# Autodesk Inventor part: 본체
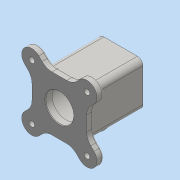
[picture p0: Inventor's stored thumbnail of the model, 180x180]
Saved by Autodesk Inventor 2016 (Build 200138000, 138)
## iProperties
Created: 2019-11
Part Number: 본체
Material: 일반
Document SubType Name: Modeling
Designer: user
Density: 1 g/cm^3
Appearance: 기본값
Author: user
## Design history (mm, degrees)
sketch "스케치1"
  geometry: L1 (49.497, 49.497)-(-49.497, -49.497); L2 (36.77, 62.225)-(-62.225, -36.77); L3 (-36.77, -62.225)-(62.225, 36.77); L4 (-49.497, 49.497)-(49.497, -49.497); L5 (-62.225, 36.77)-(36.77, -62.225); L6 (62.225, -36.77)-(-36.77, 62.225); L7 (0, 0)-(0, -25.456); L8 (49, 49)-(-49, 49); L9 (-49, 49)-(-49, -49); L10 (-49, -49)-(49, -49); L11 (49, -49)-(49, 49); L12 (49, 49)-(-49, -49); L13 (-49, 49)-(49, -49); A1 r 18 centre (49.497, 49.497) between (62.225, 36.77) and (36.77, 62.225); A2 r 18 centre (-49.497, -49.497) between (-62.225, -36.77) and (-36.77, -62.225); A3 r 18 centre (-49.497, 49.497) between (-36.77, 62.225) and (-62.225, 36.77); A4 r 18 centre (49.497, -49.497) between (36.77, -62.225) and (62.225, -36.77)
  constraints: 30 end point, 8 point on circle, 8 tangent, 4 centre point, 4 midpoint, 4 parallel, 1 horizontal, 1 perpendicular, 1 point on line, 1 vertical
  dimensions: "d0" = 70 distance of L7.start L1.end; "d1" = 36 diameter of A2; "d2" = 70 distance of L7.start L4.end; "d3" = 36 diameter of A4; "d4" = 90 deg angle of L4 L1; "d5" = 45 deg angle of L7 L1; "d6" = 98 distance of L9.end L10.end; "d7" = 98 distance of L8.end L9.end
extrude "돌출1" new body sketch "스케치1" distance "d8" = 12; taper "d9" = 0 deg
sketch "스케치2"
  geometry: L1 (-30, -40)-(30, -40); L2 (40, -30)-(40, 30); L3 (30, 40)-(-30, 40); L4 (-40, 30)-(-40, -30); L5 (-40, -40)-(40, 40); L6 (40, -40)-(-40, 40); A1 r 10 centre (-30, 30) between (-30, 40) and (-40, 30); A2 r 10 centre (-30, -30) between (-40, -30) and (-30, -40); A3 r 10 centre (30, -30) between (30, -40) and (40, -30); A4 r 10 centre (30, 30) between (40, 30) and (30, 40); 1 further point
  constraints: 12 end point, 8 point on circle, 8 point on line, 8 tangent, 4 centre point, 3 equal radius, 2 midpoint, 2 parallel, 1 horizontal, 1 perpendicular
  dimensions: "d10" = 80 distance of L6.end L5.end; "d11" = 80 distance of L6.start L5.end; "d56" = 10 radius of A1
extrude "돌출2" join sketch "스케치2" distance "d12" = 98; taper "d13" = 0 deg
sketch "스케치3"
  geometry: 2 further points
  constraints: 1 coincident
hole "구멍1" sketch "스케치3" at (0, 0) diameter "d14" = 50; stored, may be unused: countersink angle "d18" = 90 deg, drill point angle "d20" = 0 deg; dims "d15" = 6, "d16" = 4, "d17" = 2, "d19" = 12
sketch "스케치4"
  geometry: 2 further points
  constraints: 1 coincident
hole "구멍2" sketch "스케치4" at (0, 0) diameter "d21" = 50; stored, may be unused: countersink angle "d25" = 90 deg, drill point angle "d27" = 0 deg; dims "d22" = 6, "d23" = 70, "d24" = 86, "d26" = 12
node "작업 평면1"
sketch "스케치6"
  geometry: L1 (-23.544, 0)-(23.544, 0) reference; C1 r 20 at (0, 61); 1 further point
  constraints: 1 centre point, 1 vertical alignment
  dimensions: "d33" = 40 diameter of C1; "d34" = 61 distance from line of L1 C1.centre
extrude "돌출4" join sketch "스케치6" stored distance "d35" = 30; taper "d36" = 0 deg
sketch "스케치7"
  geometry: C1 r 20 at (0, 0) reference; 2 further points
  constraints: 1 coincident
hole "구멍3" sketch "스케치7" at (0, 0) diameter "d37" = 25; stored, may be unused: countersink angle "d41" = 90 deg, drill point angle "d43" = 0 deg; dims "d38" = 6, "d39" = 30, "d40" = 8, "d42" = 12
sketch "스케치8"
  geometry: L1 (0, 0)-(-49.497, 49.497); L2 (0, 0)-(0, 70); A1 r 70 centre (0, 0) between (-49.497, 49.497) and (0, 70); 1 further point
  constraints: 4 end point, 2 point on circle, 1 centre point, 1 coincident, 1 vertical
  dimensions: "d44" = 140 diameter of A1; "d45" = 45 deg angle of L2 L1
hole "구멍4" sketch "스케치8" at (-49.497, 49.497) diameter "d46" = 10; stored, may be unused: countersink angle "d50" = 90 deg, drill point angle "d52" = 0 deg; dims "d47" = 6, "d48" = 18, "d49" = 4, "d51" = 12
sketch "스케치9"
  geometry: L1 (-30, -30)-(30, -30); L2 (30, -30)-(30, 30); L3 (30, 30)-(-30, 30); L4 (-30, 30)-(-30, -30); L5 (-30, -30)-(30, 30); L6 (30, -30)-(-30, 30); 2 further points
  constraints: 12 end point, 2 midpoint, 2 parallel, 1 coincident, 1 horizontal, 1 perpendicular
  dimensions: "d57" = 60 distance of L3.end L2.end; "d58" = 60 distance of L1.end L2.end
hole "구멍5" sketch "스케치9" at (-30, 30) diameter "d59" = 3.242; stored, may be unused: countersink angle "d63" = 90 deg, drill point angle "d65" = 118 deg; dims "d60" = 8, "d61" = 18, "d62" = 4, "d64" = 10
chamfer "모따기1" distance "d72" = 1; stored, may be unused: second distance "d73" = 2, angle "d74" = 45 deg
fillet "모깎기1" dims "d75" = 3
fillet "모깎기2" dims "d76" = 25
fillet "모깎기3" dims "d77" = 3
fillet "모깎기4" dims "d78" = 3
fillet "모깎기5" dims "d79" = 3
sketch "스케치10"
  geometry: L1 (0, 0)-(60, 0) reference; C1 r 20 at (30, -49) reference; 2 further points
  constraints: 1 vertical alignment, 1 other
  dimensions: "d80" = 10 distance from line of L1 point (30, -10)
feature "엠보싱1" sketch "스케치10" dims "d81" = 0.5, "d82" = 0
node "솔리드1"
pattern_circular "원형 패턴1" dims angle "d54" = 360 deg
pattern_linear "직사각형 패턴1" dims "d68" = 60
other parameters: "d32" = -55
